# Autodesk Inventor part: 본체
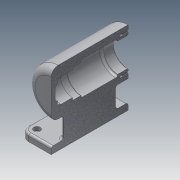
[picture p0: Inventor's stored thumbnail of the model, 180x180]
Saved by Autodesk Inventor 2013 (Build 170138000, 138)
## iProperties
Created: 2020-10
Part Number: 본체
Material: 알루미늄 6061
Document SubType Name: Modeling
Designer: 00
Density: 1 g/cm^3
Author: 00
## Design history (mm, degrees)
sketch "스케치1"
  geometry: L1 (0, 56)-(0, -56); L2 (0, 56)-(34, 56); L3 (34, 56)-(34, -56); L4 (34, -56)-(0, -56); 2 further points
  constraints: 8 end point, 2 perpendicular, 1 coincident, 1 midpoint, 1 parallel, 1 vertical
  dimensions: "d0" = 112 distance of L1.start L1.end; "d2" = 68 diameter of L3 L1
revolve "회전1" sketch "스케치1" stored, may be unused: angle "d3" = 90 deg
node "작업 평면1"
sketch "스케치2"
  geometry: L1 (-45, -56)-(45, -56); L2 (45, -56)-(45, 56); L3 (45, 56)-(-45, 56); L4 (-45, 56)-(-45, -56); L5 (-45, -56)-(45, 56); L6 (45, -56)-(-45, 56); 1 further point
  constraints: 12 end point, 2 midpoint, 2 parallel, 1 horizontal, 1 perpendicular
  dimensions: "d5" = 112 distance of L1.end L2.end; "d7" = 90 distance between parallel lines of L4 L2
extrude "돌출1" join sketch "스케치2" distance "d8" = 10; taper "d9" = 0 deg
sketch "스케치3"
  geometry: L1 (-34, -4)-(34, -4); L2 (34, -4)-(34, 4); L3 (34, 4)-(-34, 4); L4 (-34, 4)-(-34, -4); L5 (-34, -4)-(34, 4); L6 (34, -4)-(-34, 4); L7 (34, 56)-(-34, 56) reference; L8 (34, -56)-(-34, -56) reference; 1 further point
  constraints: 12 end point, 2 midpoint, 2 parallel, 1 horizontal, 1 perpendicular
  dimensions: "d10" = 8 distance of L1.end L2.end; "d12" = 68 distance between parallel lines of L4 L2
extrude "돌출2" join sketch "스케치3" stored distance "d13" = 10; taper "d14" = 0 deg
sketch "스케치4"
  geometry: L1 (34, 56)-(34, -56) reference; L2 (34, -56)-(-34, -56) reference; L3 (-34, -56)-(-34, -4) reference; L4 (-34, -4)-(-64, -4) reference; L5 (-64, -4)-(-64, -56) reference; L6 (-64, -56)-(-74, -56) reference; L7 (-74, -56)-(-74, 56) reference; L8 (-74, 56)-(-64, 56) reference; L9 (-64, 56)-(-64, 4) reference; L10 (-64, 4)-(-34, 4) reference; L11 (-34, 4)-(-34, 56) reference; L12 (-34, 56)-(34, 56) reference; L13 (-64, 38)-(-34, 38); 1 further point
  constraints: 2 end point, 2 point on line, 1 perpendicular
  dimensions: "d15" = 18 distance between parallel lines of L8 L13
feature "리브1" sketch "스케치4" dims "d16" = 1, "d17" = 8, "d18" = 0, "d19" = 0, "d20" = 1, "d21" = 1
sketch "스케치5"
  geometry: L1 (-64, 56)-(-64, 38) reference; L2 (-64, 38)-(-34, 38) reference; L3 (-34, 38)-(-34, 56) reference; L4 (-34, 56)-(34, 56) reference; L5 (34, 56)-(34, -56) reference; L6 (34, -56)-(-34, -56) reference; L7 (-34, -56)-(-34, -38) reference; L8 (-34, -38)-(-64, -38) reference; L9 (-64, -38)-(-64, -56) reference; L10 (-64, -56)-(-74, -56) reference; L11 (-74, -56)-(-74, 56) reference; L12 (-74, 56)-(-64, 56) reference; L13 (0, 56)-(0, -56); L14 (0, 50)-(10.5, 50); L15 (10.5, 50)-(10.5, 47); L16 (10.5, 47)-(16, 47); L17 (16, 47)-(16, 43); L18 (16, 43)-(17.5, 43); L19 (17.5, 43)-(17.5, 25); L20 (17.5, 25)-(21, 25); L21 (21, 25)-(21, 13); L22 (21, 13)-(24, 13); L23 (24, 13)-(24, -41); L24 (24, -41)-(21, -41); L25 (21, -41)-(21, -56); L26 (21, -56)-(0, -56); 1 further point
  constraints: 28 end point, 7 perpendicular, 5 parallel, 2 midpoint, 2 point on line, 1 collinear
  dimensions: "d22" = 15 distance of L24.end L25.end; "d24" = 54 distance of L22.end L23.end; "d25" = 12 distance of L20.end L21.end; "d26" = 18 distance of L18.end L19.end; "d27" = 4 distance of L16.end L17.end; "d28" = 3 distance of L14.end L15.end; "d29" = 42 diameter of L25 L13; "d30" = 48 diameter of L23 L13; "d31" = 42 diameter of L21 L13; "d32" = 35 diameter of L19 L13; "d33" = 32 diameter of L17 L13; "d34" = 21 diameter of L15 L13
revolve "회전2" sketch "스케치5" stored, may be unused: angle "d35" = 90 deg
fillet "모깎기1" dims "d36" = 0.3
fillet "모깎기2" dims "d37" = 3
fillet "모깎기3" dims "d38" = 12
sketch "스케치6"
  geometry: A1 r 12 centre (-33, 44) between (-33, 56) and (-45, 44) reference; A2 r 12 centre (-33, -44) between (-45, -44) and (-33, -56) reference; A3 r 12 centre (33, -44) between (33, -56) and (45, -44) reference; A4 r 12 centre (33, 44) between (45, 44) and (33, 56) reference; 5 further points
  constraints: 4 coincident
hole "구멍1" sketch "스케치6" at (-33, 44), (33, 44), (33, -44), (-33, -44) diameter "d39" = 5.5; stored, may be unused: countersink angle "d43" = 90 deg, drill point angle "d45" = 0 deg; dims "d40" = 6, "d41" = 9.5, "d42" = 5.4, "d44" = 8
fillet "모깎기4" dims "d46" = 10
sketch "스케치7"
  geometry: L1 (0, 0)-(88, 0) reference; L2 (100, 0)-(100, 10) reference; 2 further points
  constraints: 1 other
  dimensions: "d47" = 56 distance from line of L2 point (44, 3); "d48" = 3 distance from line of L1 point (44, 3)
feature "엠보싱1" sketch "스케치7" dims "d0" = 112, "d2" = 68, "d49" = 0.5, "d50" = 0
sketch "스케치8"
  geometry: C1 r 21 at (0, 0) reference; C2 r 34 at (0, 0) reference; A1 r 26 centre (0, 0) between (0, 26) and (-26, 0); 2 further points
  constraints: 4 point on circle, 2 horizontal alignment, 2 vertical alignment, 1 centre point, 1 coincident
  dimensions: "d51" = 52 diameter of A1
hole "구멍2" sketch "스케치8" at (0, 26), (-26, 0), (0, -26), (26, 0) diameter "d52" = 3.242; stored, may be unused: countersink angle "d56" = 90 deg, drill point angle "d58" = 118 deg; dims "d53" = 8, "d54" = 9.5, "d55" = 5.4, "d57" = 11
chamfer "모따기1" distance "d59" = 1; stored, may be unused: second distance "d60" = 2, angle "d61" = 45 deg
fillet "모깎기5" dims "d62" = 3
fillet "모깎기6" dims "d63" = 3
fillet "모깎기7" dims "d64" = 3
fillet "모깎기8" dims "d65" = 3
fillet "모깎기9" dims "d66" = 3
fillet "모깎기10" dims "d67" = 3
node "솔리드1"
mirror "대칭1"
node "투영된 루프1"
node "절단 모서리 투영1"
node "절단 모서리 투영2"
other parameters: "d4" = -74
